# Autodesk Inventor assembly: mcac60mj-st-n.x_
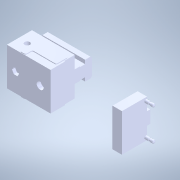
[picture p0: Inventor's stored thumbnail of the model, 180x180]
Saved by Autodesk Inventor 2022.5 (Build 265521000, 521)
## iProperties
Created: 2023-04
Part Number: mcac60mj-st-n.x_
Document SubType Name: Assembly
Designer: ImaoCorp
Sending System: SOLIDWORKS 2021-2021301
MC: AMD64
MC_MODEL: Intel64 Family 6 Model 60 Stepping 3, GenuineIntel
OS: Windows_NT
FRU: Parasolid Version 32.1, build 255,  1- 1-2021
FORMAT: text
GUISE: transmit
KEY: mcac60mj-st-n
FILE: mcac60mj-st-n.x_t
DATE: Mon Apr 10 14:38:23 2023
Author: ImaoCorp
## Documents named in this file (5)
- X:\14_SW2022-Inv2022\00_全2023-1023新製品(TCC)まで\m\mcac60mj-st-n\MCAC60MJ-ST-N.iam
- X:\14_SW2022-Inv2022\00_全2023-1023新製品(TCC)まで\m\mcac60mj-st-n\mcac60mj-st-n_01.ipt
- X:\14_SW2022-Inv2022\00_全2023-1023新製品(TCC)まで\m\mcac60mj-st-n\mcac60mj-st-n_02.ipt
- X:\14_SW2022-Inv2022\00_全2023-1023新製品(TCC)まで\m\mcac60mj-st-n\mcac60mj-st-n_03.ipt
- X:\14_SW2022-Inv2022\00_全2023-1023新製品(TCC)まで\m\mcac60mj-st-n\mcac60mj-st-n_04.ipt
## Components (4 placed, 4 different names)
1. mcac60mj-st-n_01
2. mcac60mj-st-n_02
3. mcac60mj-st-n_03
4. mcac60mj-st-n_04
